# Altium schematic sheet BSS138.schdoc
size 127 x 101 mm
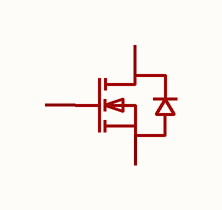
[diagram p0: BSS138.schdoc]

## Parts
Q?  bss138_c78284  [SOT-23-3_L2.9-W1.3-P1.90-LS2.4-BR]  (value not drawn)

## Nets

Not connected (* = marked no-connect by the designer): Q? 1(G) 2(S) 3(D)

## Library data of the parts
Q? = bss138_c78284: 数量:1个N沟道;漏源电压(Vdss):50V;连续漏极电流(Id):220mA;导通电阻(RDS(on)):6Ω@4.5V;耗散功率(Pd):350mW;阈值电压(Vgs(th)):800mV;; Manufacturer: CJ(江苏长电/长晶); Symbol: BSS138; AddInBom: yes; ModelId: c62791f0466c4ae2a892c056b845b0ca; ModelName: SOT-23-3P_L2.9-W1.3-H1.0-LS2.4-P0.95; ModelTransform: 98.425,114.173,0,180,0,0,0.0005,-0.0005,0; Number: 1个N沟道; Drain to Source Voltage: 50V; Current - Continuous Drain(Id): 220mA; Pd - Power Dissipation: 350mW; Gate Threshold Voltage (Vgs(th)): 800mV; Input Capacitance(Ciss): 27pF; Reverse Transfer Capacitance (Crss@Vds): 6pF; Type: N沟道; Output Capacitance(Coss): 13pF; Vgs: ±20V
